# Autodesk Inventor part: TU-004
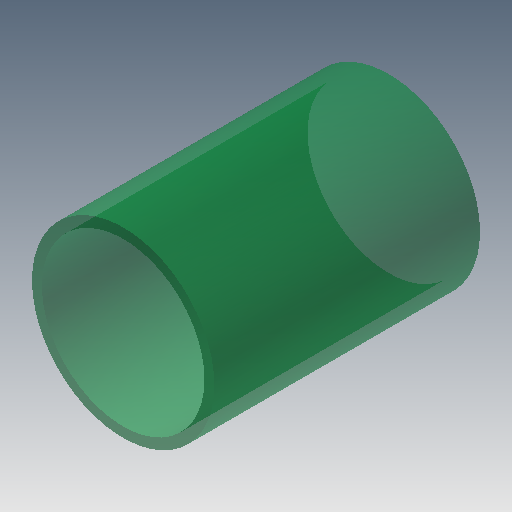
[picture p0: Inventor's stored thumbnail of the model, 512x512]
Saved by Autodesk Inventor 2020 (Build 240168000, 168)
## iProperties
Created: 2002-07
Part Number: TU-004
Document SubType Name: Modeling
Designer: PN
Description: Cylinder Tube
Density: 8.08 g/cm^3
Mass: 184.955 g
Surface Area: 189.956 cm^2
Volume: 22.8904 cm^3
Material: Stainless Steel
Appearance: Green (Clear)
Control State: 0
Master: False
Checked Out: False
Shininess: 64.0
Angle Display Precision: 2
Document Length Units: 11269
Document Angle Units: 11279
Document Time Units: 11290
Document Mass Units: 11286
Document Length Units Precision: 3
Document Angle Units Precision: 2
LENGTH: 1.000 in
Density: 0.0
Volumn: 0.0
Area: 0.0
PropertySet Name: Model Information
Author: PN
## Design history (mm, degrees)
sketch "Sketch1"
  geometry: C1 r 23 at (0, 0); C2 r 20.5 at (0, 0); 1 further point
  constraints: 2 centre point, 2 coincident
  dimensions: "d0" = 46 diameter of C1; "d1" = 41 diameter of C2
extrude "Extrusion1" new body sketch "Sketch1" stored distance "d2" = 67; taper "d3" = 0 deg
body "Solid1"
other parameters: "LENGTH" = 25.4 [user parameter]
